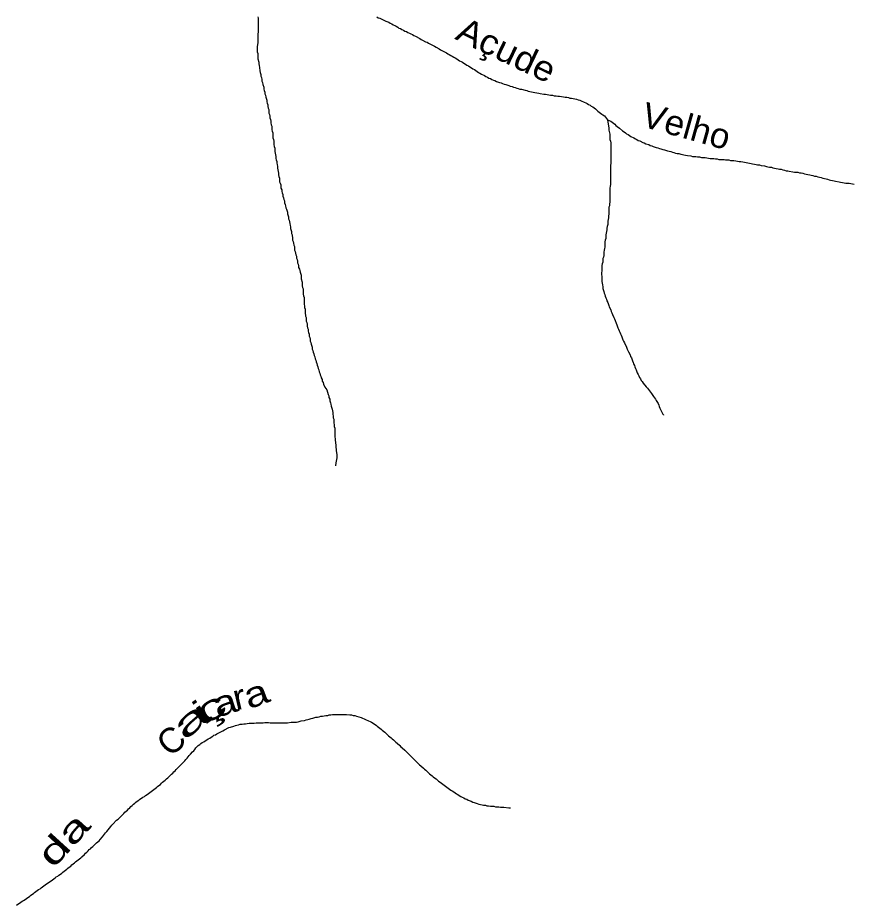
# Model space of a CAD drawing. Extents: x 652.3 to 678, y 7316.9 to 7344.9.
# Drawn here: x 672.797 to 675.469, y 7329.997 to 7332.83 of the extents above; entities that cross this region are included whole.
import ezdxf
from ezdxf.enums import TextEntityAlignment as Align

# ---------------------------------------------------------------- set-up
doc = ezdxf.new("R2010")
doc.units = 0
doc.header["$LTSCALE"] = 0.032
doc.layers.add('61', color=7, linetype='Continuous')
doc.layers.add('7', color=7, linetype='Continuous', lineweight=25)

msp = doc.modelspace()

# ---------------------------------------------------------------- linework, layer by layer
at = {"layer": '7'}
for points in [[(673.5633, 7332.8332), (673.5649, 7332.8284), (673.5649, 7332.7894), (673.5641, 7332.7838), (673.5633, 7332.7783), (673.5633, 7332.7504), (673.5625, 7332.7448), (673.5617, 7332.7377), (673.5617, 7332.721), (673.5633, 7332.7162), (673.5633, 7332.6995), (673.5665, 7332.6883), (673.5665, 7332.6828), (673.5673, 7332.6772), (673.5689, 7332.6716), (673.5704, 7332.6605), (673.5712, 7332.6549), (673.5728, 7332.6494), (673.5736, 7332.6438), (673.5752, 7332.639), (673.576, 7332.6334), (673.5768, 7332.6279), (673.5784, 7332.6231)], [(673.9436, 7332.8332), (673.9484, 7332.83), (673.9532, 7332.8284), (673.9723, 7332.8188), (673.9818, 7332.8157), (673.9866, 7332.8125), (673.9914, 7332.8109), (673.9961, 7332.8077), (674.0009, 7332.8053), (674.0057, 7332.8029), (674.0105, 7332.8005), (674.0144, 7332.7973), (674.0192, 7332.7958), (674.024, 7332.7926), (674.0288, 7332.791), (674.0335, 7332.7878), (674.0383, 7332.7862), (674.0431, 7332.783), (674.0479, 7332.7814), (674.0526, 7332.7783), (674.0574, 7332.7767), (674.0622, 7332.7735), (674.067, 7332.7711), (674.0813, 7332.7639), (674.0853, 7332.7607), (674.09, 7332.7584), (674.0996, 7332.7536), (674.1044, 7332.752), (674.1091, 7332.7488), (674.1235, 7332.7417), (674.1282, 7332.7393), (674.133, 7332.7361)], [(674.133, 7332.7361), (674.1425, 7332.7313), (674.1473, 7332.7281), (674.1664, 7332.7186), (674.1704, 7332.7154), (674.1752, 7332.713), (674.1799, 7332.7098), (674.1847, 7332.7074), (674.1895, 7332.7043), (674.1943, 7332.7019), (674.199, 7332.6987), (674.2038, 7332.6963), (674.2078, 7332.6931), (674.2126, 7332.6907), (674.2173, 7332.6883), (674.2221, 7332.6852), (674.2269, 7332.682), (674.2317, 7332.6788), (674.2364, 7332.6764), (674.2412, 7332.6732), (674.246, 7332.67), (674.2508, 7332.6669), (674.2555, 7332.6645), (674.2595, 7332.6613), (674.2643, 7332.6589), (674.2683, 7332.6557), (674.273, 7332.6533), (674.2778, 7332.6501), (674.2874, 7332.6454), (674.2921, 7332.6422), (674.2969, 7332.6406), (674.3017, 7332.6374), (674.3065, 7332.6358), (674.3112, 7332.6326), (674.316, 7332.6311), (674.3208, 7332.6295), (674.3256, 7332.6271), (674.3351, 7332.6239), (674.3407, 7332.6223), (674.3455, 7332.6199), (674.3502, 7332.6183), (674.3558, 7332.6167), (674.3653, 7332.6135), (674.3701, 7332.612), (674.3757, 7332.6104), (674.3805, 7332.6088), (674.386, 7332.6072), (674.3908, 7332.6056), (674.3956, 7332.604), (674.4004, 7332.6024), (674.4059, 7332.6016), (674.4171, 7332.5984), (674.4226, 7332.5976), (674.4274, 7332.596), (674.433, 7332.5952), (674.4378, 7332.5937), (674.4433, 7332.5929), (674.4489, 7332.5913), (674.4545, 7332.5905), (674.4608, 7332.5897), (674.4656, 7332.5881), (674.4767, 7332.5865), (674.4823, 7332.5857), (674.4879, 7332.5849), (674.4934, 7332.5841), (674.499, 7332.5825), (674.5054, 7332.5825), (674.5102, 7332.5809), (674.5165, 7332.5809), (674.5221, 7332.5801), (674.5277, 7332.5793), (674.534, 7332.5785), (674.5396, 7332.5777), (674.5452, 7332.5769), (674.5507, 7332.5769), (674.5555, 7332.5754), (674.5603, 7332.5738), (674.5659, 7332.5738), (674.5706, 7332.5722), (674.5762, 7332.5714), (674.5818, 7332.5698), (674.5865, 7332.5682), (674.5921, 7332.5666), (674.5969, 7332.565), (674.6064, 7332.5602), (674.6112, 7332.5586), (674.616, 7332.5563), (674.62, 7332.5531), (674.6247, 7332.5515), (674.6287, 7332.5483), (674.6335, 7332.5459), (674.6383, 7332.5427), (674.6422, 7332.5395), (674.6462, 7332.5356), (674.6502, 7332.5324), (674.6542, 7332.5292), (674.6582, 7332.526), (674.6621, 7332.5228), (674.6661, 7332.5197), (674.6709, 7332.5173), (674.6804, 7332.5045)], [(673.5784, 7332.6231), (673.5792, 7332.6175), (673.5824, 7332.608), (673.5824, 7332.6024), (673.584, 7332.5976), (673.5856, 7332.5929), (673.5864, 7332.5873), (673.588, 7332.5825), (673.5888, 7332.5769), (673.5919, 7332.5674), (673.5919, 7332.5618), (673.5935, 7332.5571), (673.5951, 7332.5523), (673.5951, 7332.5467), (673.5967, 7332.5419), (673.5983, 7332.5372), (673.5983, 7332.5316), (673.5991, 7332.526), (673.6007, 7332.5212), (673.6015, 7332.5157), (673.6023, 7332.5101), (673.6039, 7332.5053), (673.6047, 7332.4998), (673.6047, 7332.4942), (673.6063, 7332.4886), (673.6078, 7332.4838), (673.6078, 7332.4727), (673.6094, 7332.4679), (673.611, 7332.4632), (673.611, 7332.452), (673.6118, 7332.4465), (673.6134, 7332.4417), (673.6142, 7332.4361), (673.6142, 7332.4305), (673.615, 7332.425), (673.6158, 7332.4194), (673.6174, 7332.4138), (673.6174, 7332.4027), (673.619, 7332.3979), (673.6206, 7332.3868), (673.6206, 7332.3812), (673.6222, 7332.3764), (673.6238, 7332.3717), (673.6238, 7332.3661), (673.6254, 7332.3613), (673.6261, 7332.3557), (673.6269, 7332.3502), (673.6277, 7332.3446), (673.6285, 7332.339), (673.6301, 7332.3343), (673.6301, 7332.3287), (673.6309, 7332.3231), (673.6325, 7332.3175), (673.6333, 7332.312), (673.6333, 7332.3064), (673.6349, 7332.3016), (673.6365, 7332.2969), (673.6365, 7332.2913), (673.6373, 7332.2857), (673.6397, 7332.2809), (673.6397, 7332.2754), (673.6413, 7332.2706), (673.6429, 7332.2658), (673.6437, 7332.2603), (673.646, 7332.2555), (673.6468, 7332.2499), (673.6484, 7332.2451), (673.6492, 7332.2396), (673.6508, 7332.234), (673.6524, 7332.2292), (673.6532, 7332.2237), (673.6548, 7332.2189), (673.658, 7332.2093), (673.6588, 7332.2038), (673.662, 7332.1942), (673.662, 7332.1886), (673.6635, 7332.1839), (673.6651, 7332.1783), (673.6659, 7332.1727), (673.6667, 7332.1672), (673.6683, 7332.1624), (673.6683, 7332.1568), (673.6715, 7332.1473), (673.6715, 7332.1417), (673.6731, 7332.1369), (673.6747, 7332.1258), (673.6747, 7332.1202), (673.6763, 7332.1154), (673.6779, 7332.1107), (673.6787, 7332.1043), (673.6803, 7332.0995), (673.6811, 7332.094), (673.6811, 7332.0884), (673.6826, 7332.0836), (673.6842, 7332.0788), (673.685, 7332.0733), (673.6874, 7332.0685), (673.6874, 7332.0629), (673.689, 7332.0582), (673.6906, 7332.0534), (673.6906, 7332.0478)], [(674.6804, 7332.5045), (674.6804, 7332.5045), (674.6836, 7332.4838)], [(674.6804, 7332.5045), (674.6916, 7332.4998), (674.6956, 7332.4966), (674.6995, 7332.4934), (674.7035, 7332.4902), (674.7075, 7332.4862), (674.7115, 7332.4831), (674.7186, 7332.4775), (674.729, 7332.4695), (674.7337, 7332.4663), (674.7377, 7332.4632), (674.7417, 7332.46), (674.7465, 7332.4576), (674.7513, 7332.4544), (674.7552, 7332.4512), (674.7648, 7332.4465), (674.7696, 7332.4433), (674.7743, 7332.4417), (674.7791, 7332.4385), (674.7839, 7332.4369), (674.7934, 7332.4321), (674.7982, 7332.4305), (674.803, 7332.4281), (674.8125, 7332.425), (674.8173, 7332.4226), (674.8221, 7332.421), (674.8268, 7332.4194), (674.8364, 7332.4162), (674.8412, 7332.4146), (674.8467, 7332.413), (674.8515, 7332.4114), (674.8571, 7332.4098), (674.8626, 7332.4083), (674.8722, 7332.4051), (674.8778, 7332.4043), (674.8825, 7332.4027)], [(674.6836, 7332.4838), (674.6852, 7332.4791), (674.6852, 7332.4711), (674.6868, 7332.4632), (674.6884, 7332.4584), (674.6884, 7332.4417), (674.69, 7332.4361), (674.6916, 7332.4313), (674.6916, 7332.3645), (674.69, 7332.3597), (674.69, 7332.2977), (674.6892, 7332.2921), (674.6884, 7332.2865), (674.6884, 7332.2467), (674.6876, 7332.2412), (674.6868, 7332.2356), (674.6868, 7332.23), (674.6852, 7332.2252), (674.6852, 7332.2085), (674.6844, 7332.203), (674.6836, 7332.1974), (674.6836, 7332.1918), (674.682, 7332.1807)], [(674.8825, 7332.4027), (674.8881, 7332.4011), (674.8929, 7332.3995), (674.8977, 7332.3979), (674.9032, 7332.3971), (674.9088, 7332.3963), (674.9144, 7332.3947), (674.9199, 7332.3939), (674.9247, 7332.3923), (674.9303, 7332.3915), (674.9359, 7332.3908), (674.947, 7332.3892), (674.9518, 7332.3876), (674.9573, 7332.3876), (674.9629, 7332.3868), (674.9685, 7332.386), (674.974, 7332.386), (674.9804, 7332.3844), (674.986, 7332.3836), (674.9923, 7332.3836), (674.9979, 7332.3828), (675.0035, 7332.382), (675.0091, 7332.3812), (675.0146, 7332.3812), (675.0202, 7332.3804), (675.0258, 7332.3796), (675.0313, 7332.3796), (675.0361, 7332.378), (675.0528, 7332.378), (675.0576, 7332.3764), (675.0687, 7332.3764), (675.0735, 7332.3748), (675.0846, 7332.3748), (675.0902, 7332.3732), (675.0958, 7332.3725), (675.1014, 7332.3717), (675.1069, 7332.3717), (675.1125, 7332.3701), (675.1181, 7332.3693), (675.1236, 7332.3685), (675.1284, 7332.3669), (675.134, 7332.3661), (675.1395, 7332.3653), (675.1443, 7332.3637), (675.1499, 7332.3629), (675.1555, 7332.3621), (675.1602, 7332.3605), (675.1658, 7332.3605), (675.1714, 7332.3589), (675.1825, 7332.3573), (675.1881, 7332.3557), (675.1929, 7332.3542), (675.1984, 7332.3534), (675.204, 7332.3526), (675.2088, 7332.351), (675.2143, 7332.3502), (675.2199, 7332.3486), (675.2255, 7332.3478), (675.2303, 7332.3462), (675.2358, 7332.3462), (675.2406, 7332.3446), (675.2462, 7332.343), (675.2509, 7332.3414), (675.2565, 7332.3414), (675.2613, 7332.3398), (675.2724, 7332.3382), (675.278, 7332.3374), (675.2836, 7332.3366), (675.2891, 7332.3366), (675.2939, 7332.3351), (675.2995, 7332.3351), (675.3043, 7332.3335), (675.3098, 7332.3319), (675.3154, 7332.3303), (675.321, 7332.3295), (675.3265, 7332.3287), (675.3313, 7332.3271), (675.3369, 7332.3263), (675.3417, 7332.3247), (675.3472, 7332.3239), (675.3528, 7332.3223), (675.3576, 7332.3207), (675.3631, 7332.3199), (675.3687, 7332.3183), (675.3735, 7332.3168), (675.379, 7332.316), (675.3838, 7332.3144), (675.3886, 7332.3128), (675.3934, 7332.3112), (675.3989, 7332.3104), (675.4045, 7332.3096), (675.4093, 7332.308), (675.4204, 7332.3064), (675.4252, 7332.3048), (675.4308, 7332.304), (675.4419, 7332.3024), (675.4475, 7332.3016), (675.453, 7332.3016), (675.4634, 7332.3), (675.4681, 7332.2993), (675.4689, 7332.2992)], [(674.682, 7332.1807), (674.682, 7332.1751), (674.6812, 7332.1696), (674.6796, 7332.164), (674.6788, 7332.1584), (674.6788, 7332.1528), (674.6773, 7332.1481), (674.6765, 7332.1425), (674.6757, 7332.1369), (674.6757, 7332.1314), (674.6749, 7332.1258), (674.6733, 7332.1202), (674.6725, 7332.1146), (674.6725, 7332.0979), (674.6709, 7332.0932), (674.6701, 7332.0876), (674.6693, 7332.082), (674.6693, 7332.0709), (674.6677, 7332.0661), (674.6661, 7332.0613), (674.6661, 7332.0558), (674.6653, 7332.0502), (674.6637, 7332.0446), (674.6629, 7332.0391), (674.6629, 7332.0279), (674.6621, 7332.0223), (674.6613, 7332.0152), (674.6613, 7332.0096), (674.6629, 7332.0048), (674.6629, 7331.9881), (674.6645, 7331.977), (674.6661, 7331.9714), (674.6661, 7331.9659), (674.6693, 7331.9563), (674.6701, 7331.9507), (674.6717, 7331.946), (674.6733, 7331.9412), (674.6757, 7331.9364), (674.6773, 7331.9316), (674.6788, 7331.9261), (674.6812, 7331.9213), (674.6844, 7331.9117), (674.686, 7331.907), (674.6908, 7331.8974), (674.6924, 7331.8927), (674.6948, 7331.8879), (674.6963, 7331.8831), (674.7011, 7331.8736), (674.7027, 7331.8688), (674.7051, 7331.864), (674.7083, 7331.8545), (674.7107, 7331.8497), (674.7139, 7331.8401), (674.7162, 7331.8354), (674.7178, 7331.8306), (674.7202, 7331.8258), (674.7218, 7331.821), (674.7242, 7331.8163), (674.7266, 7331.8115), (674.7298, 7331.8019), (674.7322, 7331.7972), (674.7345, 7331.7924), (674.7417, 7331.7781), (674.7433, 7331.7725), (674.7457, 7331.7677), (674.7481, 7331.763), (674.7528, 7331.7534), (674.7544, 7331.7486), (674.7568, 7331.7439), (674.76, 7331.7343), (674.7624, 7331.7295), (674.764, 7331.7248), (674.7664, 7331.72), (674.768, 7331.7152), (674.7703, 7331.7104), (674.7727, 7331.7057), (674.7759, 7331.6961), (674.7791, 7331.6913), (674.7807, 7331.6866), (674.7831, 7331.6818), (674.7863, 7331.677), (674.7886, 7331.6722), (674.7918, 7331.6683), (674.795, 7331.6635), (674.8046, 7331.6516), (674.8085, 7331.6476), (674.8117, 7331.6436), (674.8149, 7331.6388), (674.8213, 7331.6309), (674.8276, 7331.6213), (674.8308, 7331.6165), (674.834, 7331.6126), (674.8356, 7331.6078), (674.842, 7331.5982), (674.8443, 7331.5935), (674.8459, 7331.5887), (674.8483, 7331.5839), (674.8499, 7331.5792), (674.8579, 7331.5648), (674.8594, 7331.562), (674.8596, 7331.5617)], [(673.6906, 7332.0478), (673.6922, 7332.043), (673.6938, 7332.0383), (673.6938, 7332.0327), (673.6962, 7332.0279), (673.6978, 7332.0231), (673.6986, 7332.0176), (673.7017, 7332.008), (673.7017, 7331.9969), (673.7049, 7331.9857), (673.7049, 7331.9802), (673.7057, 7331.9746), (673.7065, 7331.969), (673.7081, 7331.9643), (673.7081, 7331.9476), (673.7097, 7331.942), (673.7113, 7331.9372), (673.7113, 7331.9149), (673.7129, 7331.9102), (673.7129, 7331.9046), (673.7145, 7331.8998), (673.7145, 7331.8887), (673.7161, 7331.8775), (673.7177, 7331.8728), (673.7177, 7331.8672), (673.7184, 7331.8616), (673.72, 7331.8568), (673.7208, 7331.8513), (673.7208, 7331.8457), (673.7224, 7331.8401), (673.724, 7331.8354), (673.724, 7331.8298), (673.7256, 7331.825), (673.7272, 7331.8194), (673.7272, 7331.8139), (673.7296, 7331.8091), (673.7304, 7331.8035), (673.7312, 7331.798), (673.7328, 7331.7932), (673.7336, 7331.7876), (673.7367, 7331.7781), (673.7375, 7331.7725), (673.7391, 7331.7677), (673.7399, 7331.7622), (673.7423, 7331.7574), (673.7431, 7331.7518), (673.7455, 7331.747), (673.7463, 7331.7415), (673.7487, 7331.7367), (673.7495, 7331.7311), (673.7519, 7331.7264), (673.7527, 7331.7208), (673.755, 7331.716), (673.7558, 7331.7104), (673.7582, 7331.7057), (673.759, 7331.7001), (673.7614, 7331.6953), (673.763, 7331.6905), (673.7646, 7331.6858), (673.7662, 7331.6802), (673.7686, 7331.6754), (673.7694, 7331.6699), (673.7718, 7331.6651), (673.7734, 7331.6603), (673.7781, 7331.6508), (673.7813, 7331.6468), (673.7837, 7331.642), (673.7885, 7331.6277), (673.7901, 7331.6229), (673.7909, 7331.6173), (673.7932, 7331.6126), (673.794, 7331.607), (673.7956, 7331.6006), (673.7972, 7331.5959), (673.798, 7331.5903), (673.8012, 7331.5807), (673.8028, 7331.5696), (673.8036, 7331.564), (673.8044, 7331.5585), (673.8044, 7331.5529), (673.806, 7331.5481), (673.8068, 7331.5425), (673.8068, 7331.537), (673.8076, 7331.5306), (673.8076, 7331.525), (673.8092, 7331.5195), (673.8092, 7331.5139), (673.81, 7331.5083), (673.81, 7331.4916), (673.8107, 7331.4861), (673.8107, 7331.4805), (673.8115, 7331.4749), (673.8131, 7331.4638), (673.8131, 7331.4582), (673.8139, 7331.4526), (673.8139, 7331.4471), (673.8155, 7331.4359), (673.8155, 7331.4248), (673.8131, 7331.4089), (673.8117, 7331.3994), (673.8117, 7331.399)], [(673.1742, 7330.3251), (673.1782, 7330.3291), (673.1829, 7330.3315), (673.1869, 7330.3347), (673.1917, 7330.3379), (673.1965, 7330.3411), (673.2013, 7330.3442), (673.2052, 7330.3474), (673.21, 7330.3498), (673.214, 7330.353), (673.2188, 7330.3562), (673.2227, 7330.3594), (673.2275, 7330.3625), (673.2315, 7330.3657), (673.2355, 7330.3689), (673.2394, 7330.3721), (673.2434, 7330.3753), (673.2474, 7330.3793), (673.2522, 7330.3824), (673.2554, 7330.3864), (673.2593, 7330.3896), (673.2633, 7330.3928), (673.2673, 7330.396), (673.2713, 7330.3999), (673.276, 7330.4031), (673.28, 7330.4071), (673.284, 7330.4111), (673.288, 7330.4151), (673.292, 7330.4182), (673.2951, 7330.4222), (673.2991, 7330.4262), (673.3031, 7330.4302), (673.327, 7330.454), (673.3302, 7330.458), (673.3333, 7330.462), (673.3373, 7330.466), (673.3405, 7330.4708), (673.3445, 7330.4747), (673.3485, 7330.4787), (673.3548, 7330.4867), (673.3588, 7330.4899), (673.362, 7330.4938), (673.3652, 7330.4986), (673.3691, 7330.5026), (673.3731, 7330.5066), (673.3779, 7330.5097), (673.3819, 7330.5129), (673.3859, 7330.5161), (673.3906, 7330.5185), (673.3954, 7330.5217), (673.4002, 7330.5249), (673.4049, 7330.528), (673.4097, 7330.5304), (673.4145, 7330.5336), (673.4193, 7330.536), (673.4232, 7330.5392), (673.428, 7330.5408), (673.4328, 7330.544), (673.4471, 7330.5511), (673.4519, 7330.5535), (673.4567, 7330.5567), (673.471, 7330.5639), (673.4758, 7330.5654), (673.4869, 7330.5686), (673.4917, 7330.5702), (673.4965, 7330.5718), (673.502, 7330.5726), (673.5076, 7330.5742), (673.5132, 7330.575), (673.5187, 7330.5758), (673.5243, 7330.5758), (673.5299, 7330.5766), (673.5354, 7330.5774), (673.5466, 7330.5774), (673.5521, 7330.5782), (673.5585, 7330.579), (673.5808, 7330.579), (673.5864, 7330.5798), (673.5975, 7330.5798), (673.6031, 7330.579), (673.6588, 7330.579), (673.6699, 7330.5806), (673.6811, 7330.5806), (673.6866, 7330.5814), (673.6922, 7330.5822), (673.7017, 7330.5853), (673.7129, 7330.5869), (673.7177, 7330.5885), (673.7232, 7330.5893), (673.728, 7330.5909), (673.7336, 7330.5925), (673.7391, 7330.5933), (673.7487, 7330.5965), (673.7543, 7330.5973), (673.7598, 7330.5981), (673.7646, 7330.5997), (673.7702, 7330.5997), (673.7757, 7330.6012), (673.7813, 7330.602), (673.7869, 7330.6028), (673.7917, 7330.6044)], [(673.7917, 7330.6044), (673.7972, 7330.6044), (673.802, 7330.606), (673.8466, 7330.606), (673.8577, 7330.6044), (673.8633, 7330.6044), (673.868, 7330.6028), (673.8736, 7330.602), (673.8792, 7330.6005), (673.8935, 7330.5957), (673.8983, 7330.5941), (673.903, 7330.5917), (673.9078, 7330.5901), (673.9174, 7330.5853), (673.9221, 7330.5829), (673.9269, 7330.5806), (673.9317, 7330.5774), (673.9365, 7330.5742), (673.9412, 7330.5718), (673.9452, 7330.5686), (673.9492, 7330.5654), (673.9532, 7330.5623), (673.9572, 7330.5591), (673.9611, 7330.5559), (673.9651, 7330.5519), (673.9691, 7330.5487), (673.9731, 7330.5448), (673.977, 7330.5416), (673.981, 7330.5376), (673.985, 7330.5344), (673.989, 7330.5312), (673.993, 7330.528), (673.9969, 7330.5249), (674.0009, 7330.5209), (674.0049, 7330.5177), (674.0089, 7330.5145), (674.0168, 7330.5066), (674.0208, 7330.5026), (674.0248, 7330.4994), (674.0327, 7330.4914), (674.0367, 7330.4883), (674.0566, 7330.4684), (674.0606, 7330.4644), (674.0765, 7330.4485), (674.0805, 7330.4453), (674.0845, 7330.4421), (674.0924, 7330.4342), (674.0964, 7330.431), (674.1004, 7330.4278), (674.1044, 7330.4238), (674.1083, 7330.4198), (674.1123, 7330.4159), (674.1163, 7330.4127), (674.1203, 7330.4095), (674.1242, 7330.4063), (674.1282, 7330.4031), (674.133, 7330.3999), (674.137, 7330.396), (674.141, 7330.3928), (674.1457, 7330.3896), (674.1505, 7330.3864), (674.1545, 7330.3832), (674.1585, 7330.38), (674.1632, 7330.3769), (674.1672, 7330.3737), (674.1712, 7330.3705), (674.176, 7330.3673), (674.1799, 7330.3641), (674.1847, 7330.3617), (674.1895, 7330.3586), (674.1943, 7330.3554), (674.1982, 7330.3522), (674.203, 7330.3498), (674.207, 7330.3466), (674.2118, 7330.3442), (674.2165, 7330.3411), (674.2213, 7330.3395), (674.2261, 7330.3363), (674.2309, 7330.3347), (674.2356, 7330.3315), (674.2452, 7330.3283), (674.25, 7330.3259), (674.2547, 7330.3243), (674.2643, 7330.3212), (674.2699, 7330.3196), (674.2746, 7330.318), (674.2802, 7330.3172), (674.285, 7330.3156), (674.2905, 7330.3156), (674.2953, 7330.314), (674.3009, 7330.314), (674.3065, 7330.3132), (674.312, 7330.3124), (674.3176, 7330.3124), (674.3224, 7330.3108), (674.3335, 7330.3108), (674.3383, 7330.3092), (674.3494, 7330.3092), (674.3653, 7330.3076), (674.3701, 7330.3072), (674.3709, 7330.3071)], [(672.7923, 7329.9965), (672.797, 7329.9997), (672.8018, 7330.0029), (672.8066, 7330.0061), (672.8106, 7330.0093), (672.8153, 7330.0116), (672.8201, 7330.0148), (672.8249, 7330.018), (672.8289, 7330.0212), (672.8336, 7330.0244), (672.8376, 7330.0276), (672.8416, 7330.0307), (672.8464, 7330.0339), (672.8504, 7330.0371), (672.8543, 7330.0403), (672.8591, 7330.0435), (672.8631, 7330.0467), (672.8679, 7330.049), (672.8718, 7330.0522), (672.8758, 7330.0554), (672.8798, 7330.0586), (672.8838, 7330.0618), (672.8885, 7330.065), (672.8933, 7330.0681), (672.8981, 7330.0713), (672.9029, 7330.0745), (672.9076, 7330.0777), (672.9116, 7330.0809), (672.9156, 7330.0841), (672.9196, 7330.0872), (672.9244, 7330.0896), (672.9283, 7330.0928), (672.9331, 7330.096), (672.9371, 7330.0992), (672.9411, 7330.1024), (672.945, 7330.1055), (672.949, 7330.1087), (672.953, 7330.1119), (672.957, 7330.1151), (672.961, 7330.1183), (672.9657, 7330.1214), (672.9697, 7330.1254), (672.9737, 7330.1286), (672.9777, 7330.1318), (672.9816, 7330.135), (672.9856, 7330.1382), (672.9896, 7330.1413), (672.9936, 7330.1445), (672.9976, 7330.1477), (673.0015, 7330.1509), (673.0095, 7330.1588), (673.0135, 7330.1628), (673.0174, 7330.166), (673.0214, 7330.17), (673.0246, 7330.174), (673.0286, 7330.1771), (673.0326, 7330.1811), (673.0365, 7330.1843), (673.0405, 7330.1883), (673.0445, 7330.1923), (673.0485, 7330.1954), (673.0525, 7330.1994), (673.0564, 7330.2026), (673.0604, 7330.2066), (673.0668, 7330.2145), (673.07, 7330.2193), (673.0739, 7330.2233), (673.0771, 7330.2281), (673.0811, 7330.2321), (673.0938, 7330.248), (673.097, 7330.2519), (673.1002, 7330.2559), (673.1121, 7330.2679), (673.1169, 7330.271), (673.1201, 7330.275), (673.1241, 7330.2782), (673.132, 7330.2862), (673.136, 7330.2893), (673.1392, 7330.2933), (673.1432, 7330.2965), (673.1471, 7330.3005), (673.1503, 7330.3045), (673.1543, 7330.3076), (673.1583, 7330.3116), (673.1623, 7330.3148), (673.1662, 7330.3188), (673.1702, 7330.322), (673.1742, 7330.3251)]]:
    msp.add_lwpolyline(points, dxfattribs=at)

# ---------------------------------------------------------------- texts
at = {"layer": '61'}
for s, rotation, width, p in [('Açude', 334.473, 1.1, (674.3408, 7332.6912)), ('Velho', 344.343, 1.05, (674.9217, 7332.446)), ('a', 20.662, 1.3, (673.5714, 7330.635)), ('a', 17.938, 1.25, (673.4701, 7330.6064)), ('r', 13.014, 1.1, (673.5125, 7330.6228)), ('i', 35.125, 1.55, (673.4069, 7330.58)), ('ç', 29.811, 1.7, (673.4323, 7330.5926)), ('a', 40.439, 1.95, (673.3744, 7330.5575)), ('da', 47.671, 1.55, (672.9721, 7330.1793))]:
    msp.add_text(s, height=0.08, rotation=rotation, dxfattribs=dict(at, width=width)).set_placement(p, align=Align.CENTER)
msp.add_text('C', height=0.08, rotation=40.439, dxfattribs=at).set_placement((673.3126, 7330.4922), align=Align.CENTER)

doc.saveas('drawing.dxf')
